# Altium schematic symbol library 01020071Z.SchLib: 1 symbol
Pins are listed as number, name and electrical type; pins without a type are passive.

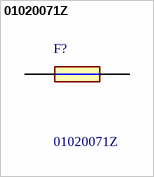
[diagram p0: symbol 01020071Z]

## 01020071Z
designator F?
Fuse Clip 15 A 250V 1 Circuit Cartridge Through Hole; Manufacturer_Name: LITTELFUSE; Geometry.Height: 10.67mm
footprint 01020071Z
pins: 1, 2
